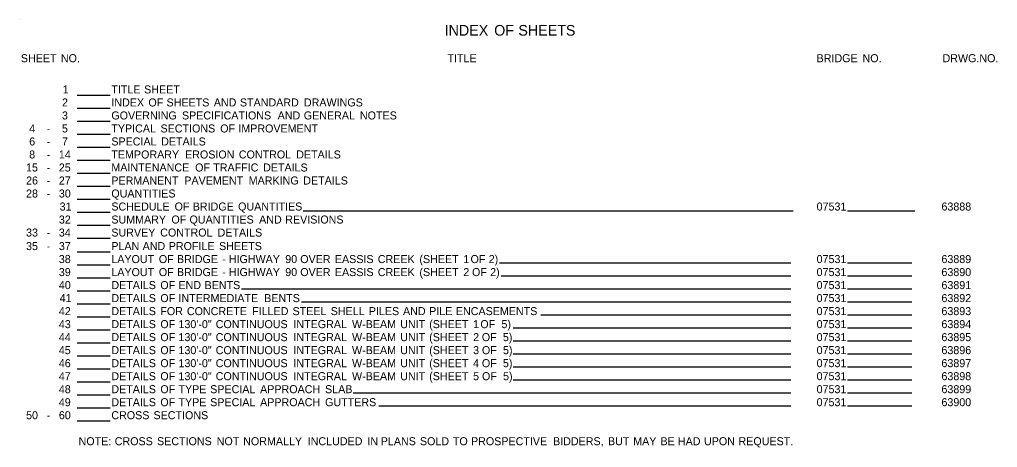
# Model space of a CAD drawing. Extents: x 2661 to 4126, y 471 to 1457.
# Drawn here: x 2661 to 3394, y 952 to 1272 of the extents above; entities that cross this region are included whole.
import ezdxf

# ---------------------------------------------------------------- set-up
doc = ezdxf.new("R2010")
doc.units = 0
doc.layers.add('Default', color=7, linetype='Continuous')

msp = doc.modelspace()

# ---------------------------------------------------------------- linework, layer by layer
at = {"layer": 'Default'}
for p, q in [((2661.23, 1272.31), (2661.23, 1272.31)), ((2704.52, 1215.76), (2729.09, 1215.76)), ((2704.52, 1206.01), (2729.09, 1206.01)), ((2704.52, 1196.26), (2729.09, 1196.26)), ((2704.52, 1186.51), (2729.09, 1186.51)), ((2704.52, 1176.76), (2729.09, 1176.76)), ((2704.52, 1167.01), (2729.09, 1167.01)), ((2704.52, 1157.26), (2729.09, 1157.26)), ((2704.52, 1147.51), (2729.09, 1147.51)), ((2704.52, 1137.76), (2729.09, 1137.76)), ((2704.52, 1128.01), (2729.09, 1128.01)), ((2873.83, 1128.99), (3241.38, 1128.99)), ((3282.12, 1128.99), (3332.61, 1128.99)), ((2704.52, 1118.26), (2729.09, 1118.26)), ((2704.52, 1108.51), (2729.09, 1108.51)), ((2704.52, 1098.37), (2729.09, 1098.37)), ((2704.52, 1088.62), (2729.09, 1088.62)), ((3021.22, 1089.99), (3239.66, 1089.99)), ((3282.12, 1089.99), (3330.34, 1089.99)), ((2704.52, 1078.87), (2729.09, 1078.87)), ((3022.41, 1080.24), (3239.66, 1080.24)), ((3282.12, 1080.24), (3330.34, 1080.24)), ((2704.52, 1069.12), (2729.09, 1069.12)), ((2827.72, 1070.49), (3239.66, 1070.49)), ((3282.12, 1070.49), (3330.34, 1070.49)), ((2704.52, 1059.37), (2729.09, 1059.37)), ((2872.75, 1060.74), (3239.66, 1060.74)), ((3282.12, 1060.74), (3330.34, 1060.74)), ((2704.52, 1049.62), (2729.09, 1049.62)), ((3052.05, 1050.99), (3239.66, 1050.99)), ((3282.12, 1050.99), (3330.34, 1050.99)), ((3031.46, 1041.24), (3239.66, 1041.24)), ((3282.12, 1041.24), (3330.34, 1041.24)), ((2704.52, 1039.87), (2729.09, 1039.87)), ((2704.52, 1030.12), (2729.09, 1030.12)), ((3031.46, 1031.49), (3239.66, 1031.49)), ((3282.12, 1031.49), (3330.34, 1031.49)), ((2704.52, 1020.37), (2729.09, 1020.37)), ((3031.46, 1021.74), (3239.66, 1021.74)), ((3282.12, 1021.74), (3330.34, 1021.74)), ((3031.46, 1011.99), (3239.66, 1011.99)), ((3282.12, 1011.99), (3330.34, 1011.99)), ((2704.52, 1010.62), (2729.09, 1010.62)), ((2704.52, 1000.87), (2729.09, 1000.87)), ((3031.46, 1002.24), (3239.66, 1002.24)), ((3282.12, 1002.24), (3330.34, 1002.24)), ((2704.52, 991.12), (2729.09, 991.12)), ((2911.45, 992.49), (3239.66, 992.49)), ((3282.12, 992.49), (3330.34, 992.49)), ((2930.58, 982.74), (3239.66, 982.74)), ((3282.12, 982.74), (3330.34, 982.74)), ((2704.52, 981.37), (2729.09, 981.37)), ((2704.52, 971.62), (2729.09, 971.62))]:
    msp.add_line(p, q, dxfattribs=at)

# ---------------------------------------------------------------- texts
for s, height, p in [('INDEX', 8, (2980, 1260.26)), (' OF', 8, (3014.16, 1260.26)), (' SHEETS', 8, (3032.27, 1260.26)), ('SHEET', 6, (2662.2, 1240.36)), (' NO.', 6, (2689.99, 1240.36)), ('TITLE', 6, (2982.07, 1240.36)), ('BRIDGE', 6, (3258.9, 1240.36)), (' NO.', 6, (3291.09, 1240.36)), ('DRWG.NO.', 6, (3353.33, 1240.36)), ('1', 6, (2693.6, 1216.96)), ('TITLE', 6, (2730.06, 1216.96)), (' SHEET', 6, (2752.44, 1216.96)), ('2', 6, (2693.05, 1207.21)), ('INDEX', 6, (2730.06, 1207.21)), (' OF', 6, (2755.63, 1207.21)), (' SHEETS', 6, (2769.22, 1207.21)), (' AND', 6, (2804.66, 1207.21)), (' STANDARD', 6, (2824.24, 1207.21)), (' DRAWINGS', 6, (2872.24, 1207.21)), ('3', 6, (2693.02, 1197.46)), ('GOVERNING', 6, (2730.06, 1197.46)), (' SPECIFICATIONS', 6, (2780.78, 1197.46)), (' AND', 6, (2852.55, 1197.46)), (' GENERAL', 6, (2872.13, 1197.46)), (' NOTES', 6, (2914.23, 1197.46)), ('4', 6, (2668.46, 1187.71)), ('-', 6, (2681.61, 1187.71)), ('5', 6, (2693, 1187.71)), ('TYPICAL', 6, (2730.06, 1187.71)), (' SECTIONS', 6, (2764.71, 1187.71)), (' OF', 6, (2809.46, 1187.71)), (' IMPROVEMENT', 6, (2823.05, 1187.71)), ('6', 6, (2668.45, 1177.96)), ('-', 6, (2681.61, 1177.96)), ('7', 6, (2693.02, 1177.96)), ('SPECIAL', 6, (2730.06, 1177.96)), (' DETAILS', 6, (2765.18, 1177.96)), ('8', 6, (2668.44, 1168.21)), ('14', 6, (2690.7, 1168.21)), ('TEMPORARY', 6, (2730.06, 1168.21)), (' EROSION', 6, (2783.11, 1168.21)), (' CONTROL', 6, (2823.42, 1168.21)), (' DETAILS', 6, (2866.44, 1168.21)), ('-', 6, (2681.61, 1168.21)), ('15', 6, (2666.1, 1158.46)), ('-', 6, (2681.61, 1158.46)), ('25', 6, (2690.67, 1158.46)), ('MAINTENANCE', 6, (2730.06, 1158.46)), (' OF', 6, (2790.64, 1158.46)), (' TRAFFIC', 6, (2804.23, 1158.46)), (' DETAILS', 6, (2841.62, 1158.46)), ('26', 6, (2666.12, 1148.71)), ('-', 6, (2681.61, 1148.71)), ('27', 6, (2690.69, 1148.71)), ('PERMANENT', 6, (2730.06, 1148.71)), (' PAVEMENT', 6, (2782.54, 1148.71)), (' MARKING', 6, (2830.82, 1148.71)), (' DETAILS', 6, (2871.75, 1148.71)), ('28', 6, (2666.11, 1138.96)), ('30', 6, (2690.7, 1138.96)), ('QUANTITIES', 6, (2730.06, 1138.96)), ('-', 6, (2681.61, 1138.96)), ('31', 6, (2691.27, 1129.21)), ('SCHEDULE', 6, (2730.06, 1129.21)), (' OF', 6, (2775.27, 1129.21)), (' BRIDGE', 6, (2788.86, 1129.21)), (' QUANTITIES', 6, (2822.89, 1129.21)), ('07531', 6, (3258.9, 1129.21)), ('63888', 6, (3352.5, 1129.21)), ('32', 6, (2690.72, 1119.46)), ('SUMMARY', 6, (2730.06, 1119.46)), (' OF', 6, (2772.86, 1119.46)), (' QUANTITIES', 6, (2786.44, 1119.46)), (' AND', 6, (2838.64, 1119.46)), (' REVISIONS', 6, (2858.22, 1119.46)), ('33', 6, (2666.12, 1109.71)), ('34', 6, (2690.7, 1109.71)), ('SURVEY', 6, (2730.06, 1109.71)), (' CONTROL', 6, (2764.48, 1109.71)), (' DETAILS', 6, (2807.5, 1109.71)), ('-', 6, (2681.61, 1109.71)), ('35', 6, (2666.1, 1099.57)), ('-', 6, (2681.61, 1099.57)), ('37', 6, (2690.69, 1099.57)), ('PLAN', 6, (2730.06, 1099.57)), (' AND', 6, (2751.28, 1099.57)), (' PROFILE', 6, (2770.86, 1099.57)), (' SHEETS', 6, (2808.61, 1099.57)), ('38', 6, (2690.68, 1089.82)), ('LAYOUT', 6, (2730.06, 1089.82)), (' OF', 6, (2763.44, 1089.82)), (' BRIDGE', 6, (2777.03, 1089.82)), (' HIGHWAY', 6, (2815.91, 1089.82)), (' 90', 6, (2858.23, 1089.82)), (' OVER', 6, (2869.47, 1089.82)), (' EASSIS', 6, (2895.45, 1089.82)), (' CREEK', 6, (2927.63, 1089.82)), (' (SHEET', 6, (2958.83, 1089.82)), (' 1', 6, (2991.73, 1089.82)), (' OF', 6, (2997.18, 1089.82)), (' 2)', 6, (3010.77, 1089.82)), ('07531', 6, (3258.9, 1089.82)), ('63889', 6, (3352.5, 1089.82)), ('39', 6, (2690.68, 1080.07)), ('LAYOUT', 6, (2730.06, 1080.07)), (' OF', 6, (2763.44, 1080.07)), (' BRIDGE', 6, (2777.03, 1080.07)), (' -', 6, (2811.05, 1089.82)), (' HIGHWAY', 6, (2815.91, 1080.07)), (' 90', 6, (2858.23, 1080.07)), (' OVER', 6, (2869.47, 1080.07)), (' EASSIS', 6, (2895.45, 1080.07)), (' CREEK', 6, (2927.63, 1080.07)), (' (SHEET', 6, (2958.83, 1080.07)), (' 2', 6, (2991.73, 1080.07)), (' OF', 6, (2998.28, 1080.07)), (' 2)', 6, (3011.86, 1080.07)), ('07531', 6, (3258.9, 1080.07)), ('63890', 6, (3352.5, 1080.07)), (' -', 6, (2811.05, 1080.07)), ('40', 6, (2690.7, 1070.32)), ('DETAILS', 6, (2730.06, 1070.32)), (' OF', 6, (2764.57, 1070.32)), (' END', 6, (2778.16, 1070.32)), (' BENTS', 6, (2797.74, 1070.32)), ('07531', 6, (3258.9, 1070.32)), ('63891', 6, (3352.5, 1070.32)), ('41', 6, (2691.27, 1060.57)), ('DETAILS', 6, (2730.06, 1060.57)), (' OF', 6, (2764.57, 1060.57)), (' INTERMEDIATE', 6, (2778.16, 1060.57)), (' BENTS', 6, (2842.45, 1060.57)), ('07531', 6, (3258.9, 1060.57)), ('63892', 6, (3352.5, 1060.57)), ('42', 6, (2690.72, 1050.82)), ('DETAILS', 6, (2730.06, 1050.82)), (' FOR', 6, (2764.57, 1050.82)), (' CONCRETE', 6, (2784.48, 1050.82)), (' FILLED', 6, (2833.41, 1050.82)), (' STEEL', 6, (2863.71, 1050.82)), (' SHELL', 6, (2892.3, 1050.82)), (' PILES', 6, (2920.89, 1050.82)), (' AND', 6, (2946.54, 1050.82)), (' PILE', 6, (2966.13, 1050.82)), (' ENCASEMENTS', 6, (2986.18, 1050.82)), ('07531', 6, (3258.9, 1050.82)), ('63893', 6, (3352.5, 1050.82)), ('43', 6, (2690.69, 1041.07)), ('DETAILS', 6, (2730.06, 1041.07)), (' OF', 6, (2764.57, 1041.07)), (' 130\'-0"', 6, (2778.16, 1041.07)), (' CONTINUOUS', 6, (2806.1, 1041.07)), (' INTEGRAL', 6, (2864.35, 1041.07)), (' W-BEAM', 6, (2908.3, 1041.07)), (' UNIT', 6, (2944.46, 1041.07)), (' (SHEET', 6, (2966.18, 1041.07)), (' 1', 6, (2999.09, 1041.07)), (' OF', 6, (3004.53, 1041.07)), ('  5)', 6, (3018.12, 1041.07)), ('07531', 6, (3258.9, 1041.07)), ('63894', 6, (3352.5, 1041.07)), ('44', 6, (2690.7, 1031.32)), ('DETAILS', 6, (2730.06, 1031.32)), (' OF', 6, (2764.57, 1031.32)), (' 130\'-0"', 6, (2778.16, 1031.32)), (' CONTINUOUS', 6, (2806.1, 1031.32)), (' INTEGRAL', 6, (2864.35, 1031.32)), (' W-BEAM', 6, (2908.3, 1031.32)), (' UNIT', 6, (2944.46, 1031.32)), (' (SHEET', 6, (2966.18, 1031.32)), (' 2', 6, (2999.09, 1031.32)), (' OF', 6, (3005.63, 1031.32)), ('  5)', 6, (3019.22, 1031.32)), ('07531', 6, (3258.9, 1031.32)), ('63895', 6, (3352.5, 1031.32)), ('45', 6, (2690.67, 1021.57)), ('DETAILS', 6, (2730.06, 1021.57)), (' OF', 6, (2764.57, 1021.57)), (' 130\'-0"', 6, (2778.16, 1021.57)), (' CONTINUOUS', 6, (2806.1, 1021.57)), (' INTEGRAL', 6, (2864.35, 1021.57)), (' W-BEAM', 6, (2908.3, 1021.57)), (' UNIT', 6, (2944.46, 1021.57)), (' (SHEET', 6, (2966.18, 1021.57)), (' 3', 6, (2999.09, 1021.57)), (' OF', 6, (3005.69, 1021.57)), ('  5)', 6, (3019.28, 1021.57)), ('07531', 6, (3258.9, 1021.57)), ('63896', 6, (3352.5, 1021.57)), ('46', 6, (2690.69, 1011.82)), ('DETAILS', 6, (2730.06, 1011.82)), (' OF', 6, (2764.57, 1011.82)), (' 130\'-0"', 6, (2778.16, 1011.82)), (' CONTINUOUS', 6, (2806.1, 1011.82)), (' INTEGRAL', 6, (2864.35, 1011.82)), (' W-BEAM', 6, (2908.3, 1011.82)), (' UNIT', 6, (2944.46, 1011.82)), (' (SHEET', 6, (2966.18, 1011.82)), (' 4', 6, (2999.09, 1011.82)), (' OF', 6, (3005.67, 1011.82)), ('  5)', 6, (3019.25, 1011.82)), ('07531', 6, (3258.9, 1011.82)), ('63897', 6, (3352.5, 1011.82)), ('47', 6, (2690.69, 1002.07)), ('DETAILS', 6, (2730.06, 1002.07)), (' OF', 6, (2764.57, 1002.07)), (' 130\'-0"', 6, (2778.16, 1002.07)), (' CONTINUOUS', 6, (2806.1, 1002.07)), (' INTEGRAL', 6, (2864.35, 1002.07)), (' W-BEAM', 6, (2908.3, 1002.07)), (' UNIT', 6, (2944.46, 1002.07)), (' (SHEET', 6, (2966.18, 1002.07)), (' 5', 6, (2999.09, 1002.07)), (' OF', 6, (3005.74, 1002.07)), ('  5)', 6, (3019.33, 1002.07)), ('07531', 6, (3258.9, 1002.07)), ('63898', 6, (3352.5, 1002.07)), ('48', 6, (2690.68, 992.32)), ('DETAILS', 6, (2730.06, 992.32)), (' OF', 6, (2764.57, 992.32)), (' TYPE', 6, (2778.16, 992.32)), (' SPECIAL', 6, (2801.94, 992.32)), (' APPROACH', 6, (2839.38, 992.32)), (' SLAB', 6, (2888.09, 992.32)), ('07531', 6, (3258.9, 992.32)), ('63899', 6, (3352.5, 992.32)), ('49', 6, (2690.68, 982.57)), ('DETAILS', 6, (2730.06, 982.57)), (' OF', 6, (2764.57, 982.57)), (' TYPE', 6, (2778.16, 982.57)), (' SPECIAL', 6, (2801.94, 982.57)), (' APPROACH', 6, (2839.38, 982.57)), (' GUTTERS', 6, (2888.09, 982.57)), ('07531', 6, (3258.9, 982.57)), ('63900', 6, (3352.5, 982.57)), ('50', 6, (2666.13, 972.82)), ('-', 6, (2681.61, 972.82)), ('60', 6, (2690.7, 972.82)), ('CROSS', 6, (2730.06, 972.82)), (' SECTIONS', 6, (2759.44, 972.82)), ('NOTE:', 6, (2705.49, 953.32)), (' CROSS', 6, (2730.38, 953.32)), (' SECTIONS', 6, (2762.09, 953.32)), (' NOT', 6, (2806.84, 953.32)), (' NORMALLY', 6, (2826.69, 953.32)), (' INCLUDED', 6, (2875.08, 953.32)), (' IN', 6, (2919.81, 953.32)), (' PLANS', 6, (2929.84, 953.32)), (' SOLD', 6, (2959.22, 953.32)), (' TO', 6, (2983.93, 953.32)), (' PROSPECTIVE', 6, (2997.52, 953.32)), (' BIDDERS,', 6, (3059.04, 953.32)), (' BUT', 6, (3100.22, 953.32)), (' MAY', 6, (3119.15, 953.32)), (' BE', 6, (3139.58, 953.32)), (' HAD', 6, (3152.65, 953.32)), (' UPON', 6, (3172.23, 953.32)), (' REQUEST.', 6, (3198.1, 953.32))]:
    msp.add_text(s, height=height, dxfattribs=at).set_placement(p)

doc.saveas('drawing.dxf')
